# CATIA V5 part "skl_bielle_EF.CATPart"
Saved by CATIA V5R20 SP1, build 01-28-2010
Part number: skl_bielle_EF
Publications: "Droite.1", "Droite.2", "Droite.3", "E", "A", "Plan.1", "Point.1", "F"
Bounding box of the stored display mesh (mm): x -20.434 to 29.779, y 0 to 30, z 45 to 82.679
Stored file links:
  C:\Users\Matthieu\Desktop\IAO_2012_mcamard_Catia\skl_bielle_EF.CATPart
  C:\Users\Matthieu\Desktop\IAO_Artobolevsky\skl_Artoboloevsky_786.CATProduct
  C:\Users\Matthieu\Desktop\IAO_2012_mcamard_Catia\skl_bielle_BD.CATPart
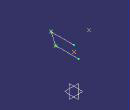
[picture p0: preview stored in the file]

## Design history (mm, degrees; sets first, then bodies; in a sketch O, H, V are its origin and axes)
Set1
  Point1 "E": linked copy from another document
  Point2 "A": linked copy from another document
  Plane1: linked copy from another document
  DatumPoint1: linked copy from another document
  Point3 "F": linked copy from another document
Set2
  Line1: type PtPt, FirstPoint Point1, SecondPoint Point3
  Line2: type PtDir, RefPoint Point1, Direction Plane1, Start 0, End 30
  Line3: type Normal, RefPoint Point3, RefSkin Plane1, Start 0, End 30
Body1 (main body)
